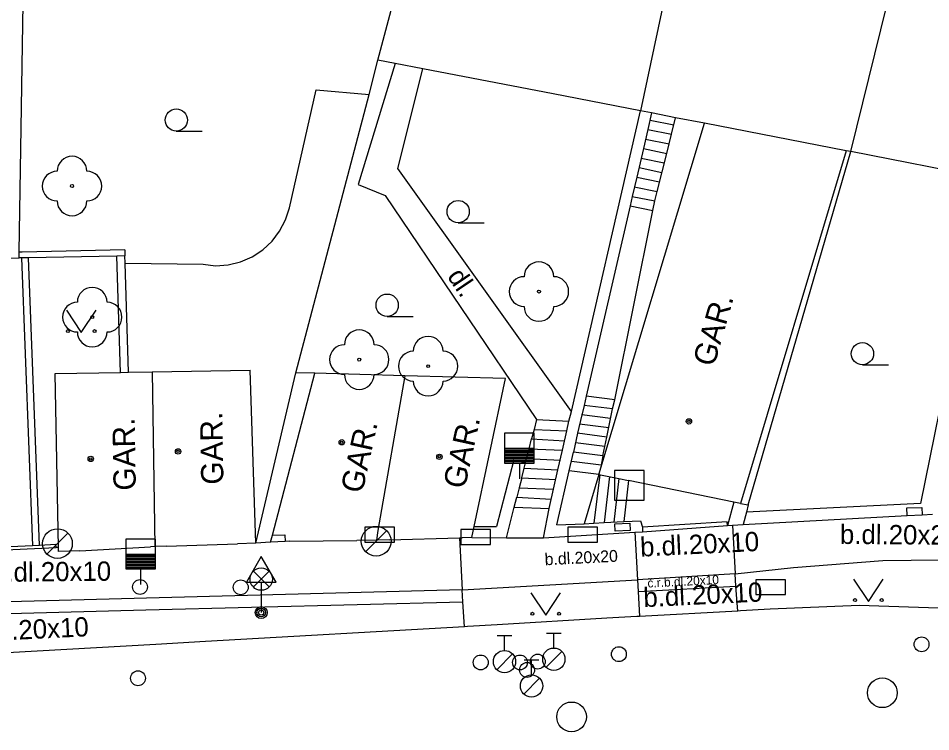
# Model space of a CAD drawing. Extents: x -595546 to -593986, y -1160845 to -1159202.
# Drawn here: x -594818.87 to -594788.15, y -1160770.3 to -1160746.29 of the extents above; entities that cross this region are included whole.
import ezdxf

# ---------------------------------------------------------------- set-up
doc = ezdxf.new("R2010")
doc.units = 0
for name, color, linetype in [('kanalizace - povrch.  znaky - skut. velikost', 7, 'Continuous'), ('Level 22', 7, 'Continuous'), ('Level 24', 7, 'Continuous'), ('Level 26', 7, 'Continuous'), ('Level 27', 7, 'Continuous'), ('Level 28', 7, 'Continuous'), ('Level 33', 7, 'Continuous'), ('Level 34', 7, 'Continuous'), ('Level 36', 7, 'Continuous'), ('Level 39', 7, 'Continuous'), ('silnoproud - povrch.  znaky a  RIS  skut. velikost', 7, 'Continuous'), ('slaboproud - povrch.  znaky a tel. budka skut. velikost', 7, 'Continuous'), ('TM - budovy zdene_ betonove - VP', 7, 'Continuous'), ('TM - chodniky - VP', 7, 'Continuous'), ('TM - komunikace - VP', 7, 'Continuous'), ('TM - letecke snimky - pomocna linie', 7, 'Continuous'), ('TM - plot drateny_ kovovy - VP', 7, 'Continuous'), ('TM - plot zdeny_ ohradni zed - VP', 7, 'Continuous'), ('TM - podezdivka plotu - VP', 7, 'Continuous'), ('TM - popis objektu', 7, 'Continuous'), ('TM - popis povrchu', 7, 'Continuous'), ('TM - rozhrani mezi zpev. plochami mezi sebou - VP', 7, 'Continuous'), ('TM - rozhrani ploch obecne - VP', 7, 'Continuous'), ('TM - schody - VP', 7, 'Continuous'), ('TM - vjezd na pozemek', 7, 'Continuous'), ('TM - vstup do budovy - zdene_ betonove', 7, 'Continuous'), ('TM - zed operna - VP', 7, 'Continuous')]:
    doc.layers.add(name, color=color, linetype=linetype)

msp = doc.modelspace()

# ---------------------------------------------------------------- linework, layer by layer
at = {"layer": 'kanalizace - povrch.  znaky - skut. velikost'}
for points in [[(-594822.95, -1160764.35), (-594817.59, -1160764.1)], [(-594818.39, -1160764.04), (-594822.12, -1160764.21)], [(-594818.15, -1160764.03), (-594818.39, -1160764.04)]]:
    msp.add_lwpolyline(points, dxfattribs=at)
at = {"layer": 'Level 22'}
for centre in [(-594817.06, -1160751.94), (-594801.34, -1160755.49), (-594816.38, -1160756.35), (-594807.39, -1160757.78), (-594805.07, -1160758)]:
    msp.add_circle(centre, 0.05, dxfattribs=at)
for centre, start, end in [((-594817.06, -1160751.44), 0, 180), ((-594817.56, -1160751.94), 90, 270), ((-594816.56, -1160751.94), 270, 90), ((-594817.06, -1160752.44), 180, 0), ((-594801.34, -1160754.99), 0, 180), ((-594801.84, -1160755.49), 90, 270), ((-594800.84, -1160755.49), 270, 90), ((-594816.38, -1160755.85), 0, 180), ((-594816.88, -1160756.35), 90, 270), ((-594815.88, -1160756.35), 270, 90), ((-594801.34, -1160755.99), 180, 0), ((-594816.38, -1160756.85), 180, 0), ((-594807.39, -1160757.28), 0, 180), ((-594805.07, -1160757.5), 0, 180), ((-594807.89, -1160757.78), 90, 270), ((-594806.89, -1160757.78), 270, 90), ((-594805.57, -1160758), 90, 270), ((-594804.57, -1160758), 270, 90), ((-594807.39, -1160758.28), 180, 0), ((-594805.07, -1160758.5), 180, 0)]:
    msp.add_arc(centre, 0.5, start, end, dxfattribs=at)
at = {"layer": 'Level 24'}
for points in [[(-594807.198, -1160763.919), (-594806.198, -1160763.919), (-594806.198, -1160763.419), (-594807.198, -1160763.419)], [(-594800.368, -1160763.919), (-594799.368, -1160763.919), (-594799.368, -1160763.419), (-594800.368, -1160763.419)], [(-594803.968, -1160763.999), (-594802.968, -1160763.999), (-594802.968, -1160763.499), (-594803.968, -1160763.499)], [(-594794.037, -1160765.688), (-594793.037, -1160765.688), (-594793.037, -1160765.188), (-594794.037, -1160765.188)]]:
    msp.add_lwpolyline(points, close=True, dxfattribs=at)
at = {"layer": 'Level 26'}
msp.add_lwpolyline([(-594798.8, -1160762.51), (-594797.8, -1160762.51), (-594797.8, -1160761.51), (-594798.8, -1160761.51)], close=True, dxfattribs=at)
at = {"layer": 'Level 27'}
for p, q in [((-594817.904, -1160764.323), (-594817.197, -1160763.616)), ((-594807.174, -1160764.243), (-594806.467, -1160763.536))]:
    msp.add_line(p, q, dxfattribs=at)
for centre in [(-594817.55, -1160763.97), (-594806.82, -1160763.89), (-594789.78, -1160768.99), (-594800.24, -1160769.8)]:
    msp.add_circle(centre, 0.5, dxfattribs=at)
at = {"layer": 'Level 28'}
for p, q in [((-594802.5, -1160760.76), (-594801.5, -1160760.76)), ((-594802.5, -1160760.81), (-594801.5, -1160760.81)), ((-594802.5, -1160760.86), (-594801.5, -1160760.86)), ((-594802.5, -1160760.91), (-594801.5, -1160760.91)), ((-594802.5, -1160760.96), (-594801.5, -1160760.96)), ((-594802.5, -1160761.01), (-594801.5, -1160761.01)), ((-594802.5, -1160761.06), (-594801.5, -1160761.06)), ((-594802.5, -1160761.11), (-594801.5, -1160761.11)), ((-594802.5, -1160761.16), (-594801.5, -1160761.16)), ((-594802.5, -1160761.21), (-594801.5, -1160761.21)), ((-594802, -1160761.26), (-594802, -1160761.79)), ((-594815.25, -1160764.32), (-594814.25, -1160764.32)), ((-594815.25, -1160764.37), (-594814.25, -1160764.37)), ((-594815.25, -1160764.42), (-594814.25, -1160764.42)), ((-594815.25, -1160764.47), (-594814.25, -1160764.47)), ((-594815.25, -1160764.52), (-594814.25, -1160764.52)), ((-594815.25, -1160764.57), (-594814.25, -1160764.57)), ((-594815.25, -1160764.62), (-594814.25, -1160764.62)), ((-594815.25, -1160764.67), (-594814.25, -1160764.67)), ((-594815.25, -1160764.72), (-594814.25, -1160764.72)), ((-594815.25, -1160764.77), (-594814.25, -1160764.77)), ((-594814.75, -1160764.82), (-594814.75, -1160765.35)), ((-594802.75, -1160767.065), (-594802.25, -1160767.065)), ((-594802.5, -1160767.565), (-594802.5, -1160767.065)), ((-594801.09, -1160766.985), (-594800.59, -1160766.985)), ((-594800.84, -1160767.485), (-594800.84, -1160766.985)), ((-594802.758, -1160768.212), (-594802.228, -1160767.682)), ((-594801.098, -1160768.132), (-594800.568, -1160767.602)), ((-594801.84, -1160767.885), (-594801.34, -1160767.885)), ((-594801.59, -1160768.385), (-594801.59, -1160767.885)), ((-594801.848, -1160769.032), (-594801.318, -1160768.502))]:
    msp.add_line(p, q, dxfattribs=at)
for points in [[(-594802.5, -1160761.26), (-594801.5, -1160761.26), (-594801.5, -1160760.26), (-594802.5, -1160760.26)], [(-594815.25, -1160764.82), (-594814.25, -1160764.82), (-594814.25, -1160763.82), (-594815.25, -1160763.82)]]:
    msp.add_lwpolyline(points, close=True, dxfattribs=at)
for centre, radius in [((-594814.77, -1160765.43), 0.25), ((-594811.38, -1160765.44), 0.25), ((-594788.46, -1160767.36), 0.25), ((-594800.84, -1160767.86), 0.375), ((-594798.65, -1160767.69), 0.25), ((-594803.3, -1160767.97), 0.25), ((-594802.5, -1160767.94), 0.375), ((-594801.98, -1160767.97), 0.25), ((-594801.38, -1160767.94), 0.25), ((-594801.74, -1160768.22), 0.25), ((-594814.84, -1160768.5), 0.25), ((-594801.59, -1160768.76), 0.375)]:
    msp.add_circle(centre, radius, dxfattribs=at)
at = {"layer": 'Level 33'}
for p, q in [((-594810.955, -1160765.43), (-594810.425, -1160764.9)), ((-594810.955, -1160764.9), (-594810.425, -1160765.43)), ((-594810.69, -1160765.54), (-594810.69, -1160766.29))]:
    msp.add_line(p, q, dxfattribs=at)
for centre, radius in [((-594810.69, -1160765.165), 0.375), ((-594810.69, -1160766.29), 0.2), ((-594810.69, -1160766.29), 0.145), ((-594810.69, -1160766.29), 0.0876)]:
    msp.add_circle(centre, radius, dxfattribs=at)
at = {"layer": 'Level 34'}
msp.add_line((-594810.69, -1160765.272), (-594810.69, -1160766.29), dxfattribs=at)
msp.add_lwpolyline([(-594811.19, -1160765.272), (-594810.19, -1160765.272), (-594810.69, -1160764.406)], close=True, dxfattribs=at)
at = {"layer": 'Level 36'}
for p, q in [((-594813.55, -1160750.095), (-594812.675, -1160750.095)), ((-594804.06, -1160753.175), (-594803.185, -1160753.175)), ((-594806.45, -1160756.325), (-594805.575, -1160756.325)), ((-594790.45, -1160757.955), (-594789.575, -1160757.955))]:
    msp.add_line(p, q, dxfattribs=at)
for points in [[(-594817.25, -1160756.12), (-594816.75, -1160756.87), (-594816.25, -1160756.12)], [(-594790.75, -1160765.17), (-594790.25, -1160765.92), (-594789.75, -1160765.17)], [(-594801.61, -1160765.63), (-594801.11, -1160766.38), (-594800.61, -1160765.63)]]:
    msp.add_lwpolyline(points, dxfattribs=at)
for centre, radius in [((-594813.55, -1160749.72), 0.375), ((-594804.06, -1160752.8), 0.375), ((-594806.45, -1160755.95), 0.375), ((-594817.2, -1160756.82), 0.05), ((-594816.301, -1160756.82), 0.05), ((-594790.45, -1160757.58), 0.375), ((-594790.7, -1160765.87), 0.05), ((-594789.801, -1160765.87), 0.05), ((-594801.56, -1160766.33), 0.05), ((-594800.661, -1160766.33), 0.05)]:
    msp.add_circle(centre, radius, dxfattribs=at)
at = {"layer": 'Level 39'}
for centre, radius in [((-594796.29, -1160759.86), 0.09), ((-594796.29, -1160759.86), 0.0398), ((-594807.98, -1160760.56), 0.09), ((-594807.98, -1160760.56), 0.0398), ((-594816.43, -1160761.12), 0.09), ((-594813.49, -1160760.87), 0.09), ((-594813.49, -1160760.87), 0.0398), ((-594804.69, -1160761.05), 0.09), ((-594804.69, -1160761.05), 0.0398), ((-594816.43, -1160761.12), 0.0398)]:
    msp.add_circle(centre, radius, dxfattribs=at)
at = {"layer": 'silnoproud - povrch.  znaky a  RIS  skut. velikost'}
for points in [[(-594798.78, -1160763.3), (-594798.28, -1160763.28)], [(-594798.77, -1160763.55), (-594798.78, -1160763.3)], [(-594798.28, -1160763.28), (-594798.27, -1160763.53)], [(-594810.31, -1160763.69), (-594809.89, -1160763.67)], [(-594809.89, -1160763.67), (-594809.88, -1160763.9)], [(-594798.27, -1160763.53), (-594798.77, -1160763.55)]]:
    msp.add_lwpolyline(points, dxfattribs=at)
at = {"layer": 'slaboproud - povrch.  znaky a tel. budka skut. velikost'}
for points in [[(-594788.95, -1160762.77), (-594788.45, -1160762.75)], [(-594788.94, -1160763.03), (-594788.95, -1160762.77)], [(-594788.45, -1160762.75), (-594788.44, -1160763)]]:
    msp.add_lwpolyline(points, dxfattribs=at)
at = {"layer": 'TM - budovy zdene_ betonove - VP'}
for points in [[(-594795.83, -1160739.6), (-594797.92, -1160749.41)], [(-594790.84, -1160750.78), (-594788.42, -1160740.94)], [(-594806.76, -1160747.71), (-594806.31, -1160746.02)], [(-594806.18, -1160747.82), (-594806.76, -1160747.71)], [(-594805.25, -1160748), (-594806.18, -1160747.82)], [(-594797.92, -1160749.41), (-594800.86, -1160748.84), (-594805.25, -1160748)], [(-594797.55, -1160749.48), (-594797.92, -1160749.41)], [(-594796.74, -1160749.64), (-594797.55, -1160749.48)], [(-594795.77, -1160749.83), (-594796.74, -1160749.64)], [(-594799.32, -1160761.64), (-594795.77, -1160749.83)], [(-594791, -1160750.75), (-594795.77, -1160749.83)], [(-594791, -1160750.75), (-594794.56, -1160762.62)], [(-594790.84, -1160750.78), (-594791, -1160750.75)], [(-594786.27, -1160751.67), (-594790.84, -1160750.78)], [(-594817.63, -1160758.25), (-594815.43, -1160758.21)], [(-594817.52, -1160764.1), (-594817.63, -1160758.25)], [(-594815.43, -1160758.21), (-594815.16, -1160758.2)], [(-594815.16, -1160758.2), (-594814.36, -1160758.19)], [(-594814.36, -1160758.19), (-594811.06, -1160758.13)], [(-594814.36, -1160758.19), (-594814.27, -1160764.07)], [(-594810.87, -1160763.95), (-594811.06, -1160758.13)], [(-594810.31, -1160763.69), (-594808.89, -1160758.24)], [(-594805.85, -1160758.32), (-594808.89, -1160758.24)], [(-594805.85, -1160758.32), (-594806.76, -1160763.53)], [(-594802.47, -1160758.42), (-594805.85, -1160758.32)], [(-594803.52, -1160763.4), (-594802.47, -1160758.42)], [(-594799.32, -1160761.64), (-594798.65, -1160761.78), (-594798.32, -1160761.85)], [(-594794.78, -1160762.58), (-594798.32, -1160761.85)], [(-594794.56, -1160762.62), (-594794.78, -1160762.58)], [(-594803.6, -1160763.77), (-594803.52, -1160763.4)], [(-594810.38, -1160763.92), (-594810.31, -1160763.69)], [(-594806.76, -1160763.53), (-594806.81, -1160763.85)], [(-594803.6, -1160763.77), (-594803.92, -1160763.78)], [(-594817.52, -1160764.24), (-594817.52, -1160764.1)], [(-594814.27, -1160764.07), (-594814.42, -1160764.08)], [(-594813.88, -1160764.06), (-594814.27, -1160764.07)], [(-594810.87, -1160763.95), (-594811.49, -1160763.98)], [(-594809.88, -1160763.9), (-594810.38, -1160763.92)], [(-594809.74, -1160763.89), (-594809.88, -1160763.9)], [(-594806.81, -1160763.85), (-594807.47, -1160763.87)], [(-594806.38, -1160763.84), (-594806.81, -1160763.85)], [(-594816.8, -1160764.21), (-594817.52, -1160764.24)]]:
    msp.add_lwpolyline(points, dxfattribs=at)
at = {"layer": 'TM - chodniky - VP'}
for points in [[(-594806.18, -1160747.82), (-594807.43, -1160751.89), (-594806.52, -1160752.26), (-594801.42, -1160759.8)], [(-594806.09, -1160751.35), (-594805.25, -1160748)], [(-594800.25, -1160759.52), (-594806.09, -1160751.35)], [(-594818.15, -1160764.03), (-594818.52, -1160754.35)], [(-594801.42, -1160759.8), (-594801.5, -1160760.13)], [(-594801.5, -1160760.13), (-594801.59, -1160760.45)], [(-594801.79, -1160761.25), (-594801.76, -1160761.11), (-594801.67, -1160760.78), (-594801.59, -1160760.45)], [(-594817.59, -1160764.1), (-594817.6, -1160764), (-594818.15, -1160764.03)], [(-594817.52, -1160764.1), (-594817.59, -1160764.1)], [(-594792.77, -1160764.77), (-594789.76, -1160764.54)], [(-594789.76, -1160764.54), (-594786.89, -1160764.51)], [(-594794.73, -1160764.99), (-594792.77, -1160764.77)], [(-594794.71, -1160765.4), (-594794.73, -1160764.99)], [(-594803.92, -1160765.52), (-594798.02, -1160765.19)], [(-594798.02, -1160765.19), (-594798, -1160765.58)], [(-594803.9, -1160765.93), (-594803.92, -1160765.52)], [(-594798, -1160765.58), (-594797.95, -1160766.42)], [(-594794.65, -1160766.24), (-594794.71, -1160765.4)], [(-594803.85, -1160766.77), (-594803.9, -1160765.93)]]:
    msp.add_lwpolyline(points, dxfattribs=at)
at = {"layer": 'TM - komunikace - VP'}
for points in [[(-594794.65, -1160766.24), (-594797.95, -1160766.42)], [(-594794.56, -1160766.23), (-594794.65, -1160766.24)], [(-594793.56, -1160766.18), (-594794.56, -1160766.23)], [(-594790.56, -1160766.05), (-594793.56, -1160766.18)], [(-594787.56, -1160766.15), (-594790.56, -1160766.05)], [(-594799.05, -1160766.48), (-594802.75, -1160766.7)], [(-594798.04, -1160766.42), (-594799.05, -1160766.48)], [(-594797.95, -1160766.42), (-594798.04, -1160766.42)], [(-594803.85, -1160766.77), (-594812.57, -1160767.26), (-594814.24, -1160767.36)], [(-594803.75, -1160766.76), (-594803.85, -1160766.77)], [(-594802.75, -1160766.7), (-594803.75, -1160766.76)], [(-594814.24, -1160767.36), (-594826.44, -1160768.05)]]:
    msp.add_lwpolyline(points, dxfattribs=at)
at = {"layer": 'TM - letecke snimky - pomocna linie'}
for points in [[(-594818.84, -1160754.16), (-594818.68, -1160744.4), (-594818.4, -1160743.3), (-594818.11, -1160742.58), (-594817.8, -1160741.97), (-594817.08, -1160741.35), (-594816.35, -1160740.93), (-594814.07, -1160741.45), (-594812.8, -1160741.72)], [(-594815.27, -1160754.53), (-594812.65, -1160754.57), (-594812.23, -1160754.62), (-594811.8, -1160754.59), (-594811.39, -1160754.49), (-594810.99, -1160754.32), (-594810.64, -1160754.09), (-594810.32, -1160753.8), (-594810.07, -1160753.46), (-594809.87, -1160753.08), (-594809.74, -1160752.67), (-594808.84, -1160748.7), (-594807.06, -1160748.86)]]:
    msp.add_lwpolyline(points, dxfattribs=at)
at = {"layer": 'TM - plot drateny_ kovovy - VP'}
for points in [[(-594822.32, -1160754.43), (-594818.84, -1160754.36)], [(-594815.27, -1160754.53), (-594815.28, -1160754.29)], [(-594815.16, -1160758.2), (-594815.27, -1160754.53)]]:
    msp.add_lwpolyline(points, dxfattribs=at)
at = {"layer": 'TM - plot zdeny_ ohradni zed - VP'}
for points in [[(-594786.27, -1160751.67), (-594788.5, -1160762.62)], [(-594815.28, -1160754.09), (-594818.74, -1160754.16), (-594818.84, -1160754.16)], [(-594788.5, -1160762.62), (-594794.35, -1160762.91)], [(-594810.38, -1160763.92), (-594810.87, -1160763.95)]]:
    msp.add_lwpolyline(points, dxfattribs=at)
at = {"layer": 'TM - podezdivka plotu - VP'}
for points in [[(-594800.25, -1160759.52), (-594797.92, -1160749.41)], [(-594818.84, -1160754.36), (-594818.84, -1160754.16)], [(-594815.28, -1160754.09), (-594815.28, -1160754.29)], [(-594818.76, -1160754.36), (-594818.84, -1160754.36)], [(-594818.52, -1160754.35), (-594818.76, -1160754.36)], [(-594815.55, -1160754.3), (-594818.52, -1160754.35)], [(-594815.28, -1160754.29), (-594815.55, -1160754.3)], [(-594815.43, -1160758.21), (-594815.55, -1160754.3)], [(-594800.33, -1160759.85), (-594800.25, -1160759.52)], [(-594800.55, -1160760.83), (-594800.4, -1160760.18), (-594800.33, -1160759.85)], [(-594801, -1160762.79), (-594800.85, -1160762.14), (-594800.7, -1160761.49), (-594800.55, -1160760.83)], [(-594802.19, -1160761.15), (-594801.79, -1160761.25)], [(-594801.92, -1160761.76), (-594801.84, -1160761.43), (-594801.79, -1160761.25)], [(-594801.92, -1160761.76), (-594802.01, -1160762.09)], [(-594802.01, -1160762.09), (-594802.09, -1160762.41)], [(-594802.18, -1160762.74), (-594802.09, -1160762.41)], [(-594802.43, -1160763.78), (-594802.18, -1160762.74)], [(-594801.19, -1160763.78), (-594801, -1160762.79)], [(-594794.78, -1160762.58), (-594794.99, -1160763.36)], [(-594794.56, -1160762.62), (-594794.3, -1160762.67)], [(-594794.46, -1160763.33), (-594788.94, -1160763.03)], [(-594788.94, -1160763.03), (-594788.44, -1160763)], [(-594788.44, -1160763), (-594788.09, -1160762.98)], [(-594797.92, -1160763.2), (-594797.85, -1160763.42)], [(-594797.85, -1160763.42), (-594797.85, -1160763.57)], [(-594794.99, -1160763.36), (-594794.82, -1160763.35)], [(-594794.82, -1160763.35), (-594794.46, -1160763.33)], [(-594803.6, -1160763.77), (-594802.43, -1160763.78)], [(-594801.19, -1160763.78), (-594798.11, -1160763.59)], [(-594798.11, -1160763.59), (-594797.85, -1160763.57)]]:
    msp.add_lwpolyline(points, dxfattribs=at)
at = {"layer": 'TM - rozhrani mezi zpev. plochami mezi sebou - VP'}
for points in [[(-594818.76, -1160754.36), (-594818.39, -1160764.04)], [(-594795, -1160763.24), (-594797.85, -1160763.42)], [(-594794.99, -1160763.36), (-594795, -1160763.24)], [(-594794.82, -1160763.35), (-594794.73, -1160764.99)], [(-594804.01, -1160763.78), (-594803.92, -1160765.52)], [(-594798.11, -1160763.59), (-594798.02, -1160765.19)], [(-594794.73, -1160764.99), (-594798.02, -1160765.19)], [(-594803.92, -1160765.52), (-594814.55, -1160765.81)], [(-594798, -1160765.58), (-594794.71, -1160765.4)], [(-594814.55, -1160765.81), (-594826.34, -1160766.12)], [(-594814.58, -1160766.2), (-594803.9, -1160765.93)], [(-594826.3, -1160766.51), (-594814.58, -1160766.2)]]:
    msp.add_lwpolyline(points, dxfattribs=at)
at = {"layer": 'TM - rozhrani ploch obecne - VP'}
for points in [[(-594807.06, -1160748.86), (-594806.76, -1160747.71)], [(-594809.52, -1160758.22), (-594807.06, -1160748.86)], [(-594797.51, -1160752.76), (-594797.44, -1160752.44), (-594797.36, -1160752.12), (-594797.04, -1160750.84), (-594796.96, -1160750.52), (-594796.88, -1160750.2), (-594796.74, -1160749.64)], [(-594794.3, -1160762.67), (-594790.84, -1160750.78)], [(-594798.27, -1160752.61), (-594797.51, -1160752.76)], [(-594798.79, -1160759.13), (-594797.51, -1160752.76)], [(-594810.87, -1160763.95), (-594809.52, -1160758.22)], [(-594808.89, -1160758.24), (-594809.52, -1160758.22)], [(-594798.79, -1160759.13), (-594799.75, -1160759.01)], [(-594799.19, -1160761.02), (-594799.06, -1160760.39), (-594798.86, -1160759.44), (-594798.79, -1160759.13)], [(-594801.42, -1160759.8), (-594800.33, -1160759.85)], [(-594799.19, -1160761.02), (-594799.25, -1160761.33)], [(-594799.25, -1160761.33), (-594799.32, -1160761.64)], [(-594799.32, -1160761.64), (-594800.32, -1160761.52)], [(-594799.32, -1160761.64), (-594799.82, -1160763.3)], [(-594798.32, -1160761.85), (-594798.48, -1160763.23)], [(-594802.18, -1160762.74), (-594801, -1160762.79)]]:
    msp.add_lwpolyline(points, dxfattribs=at)
at = {"layer": 'TM - schody - VP'}
for points in [[(-594797.6, -1160749.72), (-594796.8, -1160749.88)], [(-594797.67, -1160750.04), (-594796.88, -1160750.2)], [(-594797.75, -1160750.36), (-594796.96, -1160750.52)], [(-594797.82, -1160750.68), (-594797.04, -1160750.84)], [(-594797.9, -1160751), (-594797.12, -1160751.16)], [(-594797.97, -1160751.32), (-594797.2, -1160751.48)], [(-594798.05, -1160751.64), (-594797.28, -1160751.8)], [(-594798.13, -1160751.97), (-594797.36, -1160752.12)], [(-594798.2, -1160752.29), (-594797.44, -1160752.44)], [(-594798.86, -1160759.44), (-594799.82, -1160759.32)], [(-594798.93, -1160759.76), (-594799.9, -1160759.64)], [(-594798.99, -1160760.07), (-594799.97, -1160759.95)], [(-594801.5, -1160760.13), (-594800.4, -1160760.18)], [(-594799.06, -1160760.39), (-594800.04, -1160760.26)], [(-594801.59, -1160760.45), (-594800.48, -1160760.51)], [(-594799.12, -1160760.7), (-594800.11, -1160760.58)], [(-594801.67, -1160760.78), (-594800.55, -1160760.83)], [(-594799.19, -1160761.02), (-594800.18, -1160760.89)], [(-594801.76, -1160761.11), (-594800.62, -1160761.16)], [(-594799.25, -1160761.33), (-594800.25, -1160761.21)], [(-594801.84, -1160761.43), (-594800.7, -1160761.49)], [(-594799.29, -1160761.65), (-594799.49, -1160763.28)], [(-594801.92, -1160761.76), (-594800.77, -1160761.81)], [(-594798.97, -1160761.71), (-594799.15, -1160763.26)], [(-594798.65, -1160761.78), (-594798.82, -1160763.25)], [(-594802.01, -1160762.09), (-594800.85, -1160762.14)], [(-594802.09, -1160762.41), (-594800.93, -1160762.47)]]:
    msp.add_lwpolyline(points, dxfattribs=at)
at = {"layer": 'TM - vjezd na pozemek'}
for points in [[(-594797.85, -1160763.57), (-594794.99, -1160763.36)], [(-594802.43, -1160763.78), (-594801.19, -1160763.78)]]:
    msp.add_lwpolyline(points, dxfattribs=at)
at = {"layer": 'TM - vstup do budovy - zdene_ betonove'}
for points in [[(-594806.38, -1160763.84), (-594804.01, -1160763.78)], [(-594804.01, -1160763.78), (-594803.92, -1160763.78)], [(-594816.8, -1160764.21), (-594814.42, -1160764.08)], [(-594813.88, -1160764.06), (-594811.49, -1160763.98)], [(-594809.74, -1160763.89), (-594807.47, -1160763.87)]]:
    msp.add_lwpolyline(points, dxfattribs=at)
at = {"layer": 'TM - zed operna - VP'}
for points in [[(-594797.55, -1160749.48), (-594797.67, -1160750.04), (-594797.82, -1160750.68), (-594798.05, -1160751.64), (-594798.2, -1160752.29), (-594798.27, -1160752.61)], [(-594798.27, -1160752.61), (-594799.75, -1160759.01)], [(-594799.75, -1160759.01), (-594799.82, -1160759.32), (-594799.89, -1160759.6), (-594799.9, -1160759.64), (-594800.04, -1160760.26), (-594800.18, -1160760.89)], [(-594800.32, -1160761.52), (-594800.18, -1160760.89)], [(-594802.19, -1160761.15), (-594802.77, -1160763.39)], [(-594800.74, -1160763.34), (-594800.32, -1160761.52)], [(-594794.3, -1160762.67), (-594794.35, -1160762.91)], [(-594794.35, -1160762.91), (-594794.46, -1160763.33)], [(-594803.52, -1160763.4), (-594802.77, -1160763.39)], [(-594800.74, -1160763.34), (-594799.82, -1160763.3)], [(-594799.82, -1160763.3), (-594799.49, -1160763.28), (-594799.15, -1160763.26), (-594798.48, -1160763.23)], [(-594798.48, -1160763.23), (-594797.92, -1160763.2)]]:
    msp.add_lwpolyline(points, dxfattribs=at)

# ---------------------------------------------------------------- texts
at = {"layer": 'TM - popis objektu'}
for rotation, p in [(74.07, (-594795.45, -1160758.05)), (90.94, (-594811.96, -1160761.98)), (90.94, (-594814.91, -1160762.18)), (77.61, (-594807.29, -1160762.31)), (77.61, (-594803.84, -1160762.16))]:
    msp.add_text('GAR.', height=0.75, rotation=rotation, dxfattribs=at).set_placement(p)
at = {"layer": 'TM - popis povrchu'}
for s, height, rotation, p in [('dl.', 0.65, 304.0741, (-594804.45, -1160754.98)), ('b.dl.20x20', 0.65, 359.5786, (-594791.21, -1160763.98)), ('b.dl.20x10', 0.65, 2.7698, (-594797.92, -1160764.41)), ('b.dl.20x20', 0.4, 2.8436, (-594801.14, -1160764.7)), ('b.dl.20x10', 0.65, 0.599, (-594819.75, -1160765.26)), ('č.r.b.dl.20x10', 0.3, 2.8555, (-594797.68, -1160765.45)), ('b.dl.20x10', 0.65, 2.7698, (-594797.81, -1160766.11)), ('b.dl.20x10', 0.65, 2.7698, (-594820.49, -1160767.28))]:
    msp.add_text(s, height=height, rotation=rotation, dxfattribs=at).set_placement(p)

doc.saveas('drawing.dxf')
